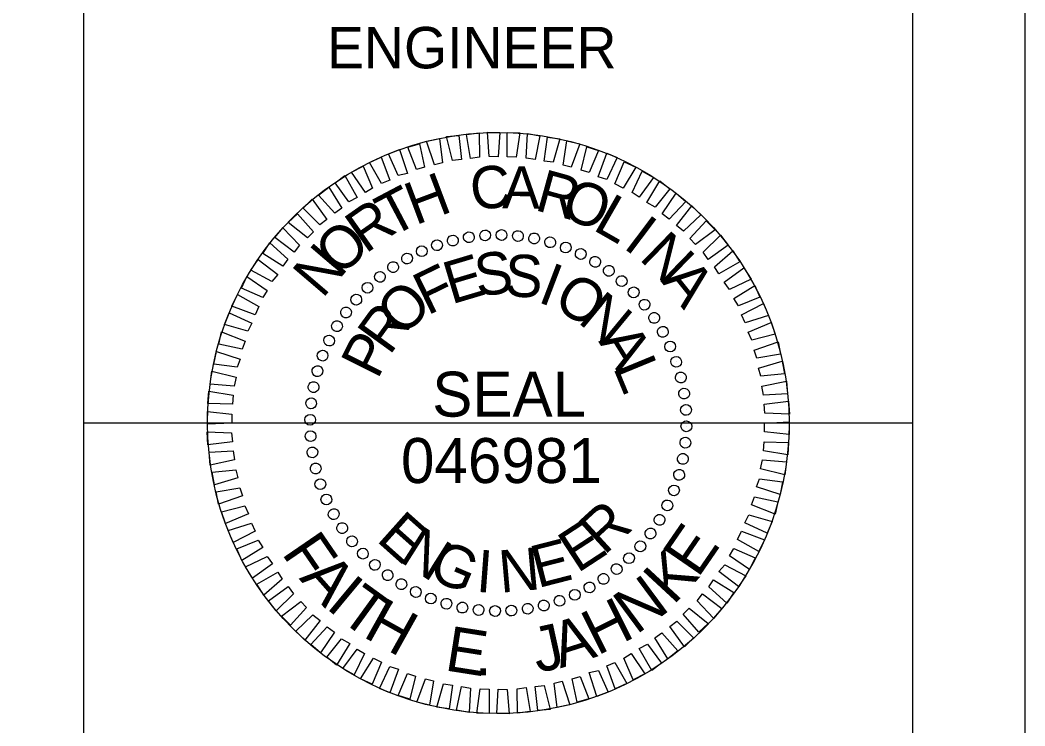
# Model space of a CAD drawing. Extents: x 1184048.9 to 1184122, y 1246638.9 to 1246660.6.
# Drawn here: x 1184112.634 to 1184115.034, y 1246656.132 to 1246657.819 of the extents above; entities that cross this region are included whole.
import ezdxf

# ---------------------------------------------------------------- set-up
doc = ezdxf.new("R2010")
doc.units = 0
for name, color, linetype in [('Scratch_Level_3', 7, 'Continuous'), ('Sheet PE Seal CELL', 7, 'Continuous'), ('Sheet Plan CELL', 7, 'Continuous'), ('Sheet Plot Border Outside CELL', 7, 'Continuous')]:
    doc.layers.add(name, color=color, linetype=linetype)

msp = doc.modelspace()

# ---------------------------------------------------------------- linework, layer by layer
at = {"layer": 'Scratch_Level_3'}
msp.add_line((1184114.7665, 1246656.856), (1184112.7859, 1246656.856), dxfattribs=at)
msp.add_circle((1184113.7762, 1246656.856), 0.6945, dxfattribs=at)
at = {"layer": 'Sheet PE Seal CELL'}
for p, q in [((1184113.6669, 1246657.2923), (1184113.6669, 1246657.2923)), ((1184113.7063, 1246657.2995), (1184113.7063, 1246657.2995)), ((1184113.7448, 1246657.3048), (1184113.7448, 1246657.3048)), ((1184113.7843, 1246657.3057), (1184113.7843, 1246657.3057)), ((1184113.8237, 1246657.3031), (1184113.8237, 1246657.3031)), ((1184113.8622, 1246657.2968), (1184113.8622, 1246657.2968)), ((1184113.8998, 1246657.2887), (1184113.8998, 1246657.2887)), ((1184113.5934, 1246657.2672), (1184113.5934, 1246657.2672)), ((1184113.6293, 1246657.2816), (1184113.6293, 1246657.2816)), ((1184113.9375, 1246657.2762), (1184113.9375, 1246657.2762)), ((1184113.9733, 1246657.2601), (1184113.9733, 1246657.2601)), ((1184113.5585, 1246657.2493), (1184113.5585, 1246657.2493)), ((1184114.0082, 1246657.2421), (1184114.0082, 1246657.2421)), ((1184113.5244, 1246657.2287), (1184113.5244, 1246657.2287)), ((1184114.0405, 1246657.2197), (1184114.0405, 1246657.2197)), ((1184113.4931, 1246657.2063), (1184113.4931, 1246657.2063)), ((1184114.0719, 1246657.1955), (1184114.0719, 1246657.1955)), ((1184113.4635, 1246657.1794), (1184113.4635, 1246657.1794)), ((1184114.0996, 1246657.1687), (1184114.0996, 1246657.1687)), ((1184113.4366, 1246657.1516), (1184113.4366, 1246657.1516)), ((1184114.1265, 1246657.1391), (1184114.1265, 1246657.1391)), ((1184113.4124, 1246657.1203), (1184113.4124, 1246657.1203)), ((1184114.1489, 1246657.1077), (1184114.1489, 1246657.1077)), ((1184113.39, 1246657.088), (1184113.39, 1246657.088)), ((1184114.1695, 1246657.0737), (1184114.1695, 1246657.0737)), ((1184113.3721, 1246657.0531), (1184113.3721, 1246657.0531)), ((1184114.1874, 1246657.0388), (1184114.1874, 1246657.0388)), ((1184113.356, 1246657.0173), (1184113.356, 1246657.0173)), ((1184114.2018, 1246657.0029), (1184114.2018, 1246657.0029)), ((1184113.3435, 1246656.9796), (1184113.3435, 1246656.9796)), ((1184114.2125, 1246656.9653), (1184114.2125, 1246656.9653)), ((1184113.3354, 1246656.942), (1184113.3354, 1246656.942)), ((1184114.2197, 1246656.9259), (1184114.2197, 1246656.9259)), ((1184113.3291, 1246656.9035), (1184113.3291, 1246656.9035)), ((1184114.2251, 1246656.8873), (1184114.2251, 1246656.8873)), ((1184113.3264, 1246656.864), (1184113.3264, 1246656.864)), ((1184113.7762, 1246656.856), (1184113.7762, 1246656.856)), ((1184114.226, 1246656.8479), (1184114.226, 1246656.8479)), ((1184113.3273, 1246656.8246), (1184113.3273, 1246656.8246)), ((1184114.2233, 1246656.8085), (1184114.2233, 1246656.8085)), ((1184113.3327, 1246656.7861), (1184113.3327, 1246656.7861)), ((1184114.217, 1246656.77), (1184114.217, 1246656.77)), ((1184113.3399, 1246656.7467), (1184113.3399, 1246656.7467)), ((1184114.2089, 1246656.7323), (1184114.2089, 1246656.7323)), ((1184113.3506, 1246656.709), (1184113.3506, 1246656.709)), ((1184114.1964, 1246656.6947), (1184114.1964, 1246656.6947)), ((1184113.365, 1246656.6732), (1184113.365, 1246656.6732)), ((1184114.1803, 1246656.6589), (1184114.1803, 1246656.6589)), ((1184113.3829, 1246656.6383), (1184113.3829, 1246656.6383)), ((1184114.1624, 1246656.6239), (1184114.1624, 1246656.6239)), ((1184113.4035, 1246656.6042), (1184113.4035, 1246656.6042)), ((1184114.14, 1246656.5917), (1184114.14, 1246656.5917)), ((1184113.4259, 1246656.5729), (1184113.4259, 1246656.5729)), ((1184113.4528, 1246656.5433), (1184113.4528, 1246656.5433)), ((1184114.1158, 1246656.5603), (1184114.1158, 1246656.5603)), ((1184113.4805, 1246656.5164), (1184113.4805, 1246656.5164)), ((1184114.0889, 1246656.5325), (1184114.0889, 1246656.5325)), ((1184113.5119, 1246656.4922), (1184113.5119, 1246656.4922)), ((1184114.0593, 1246656.5057), (1184114.0593, 1246656.5057)), ((1184113.5441, 1246656.4698), (1184113.5441, 1246656.4698)), ((1184114.028, 1246656.4833), (1184114.028, 1246656.4833)), ((1184113.5791, 1246656.4519), (1184113.5791, 1246656.4519)), ((1184113.959, 1246656.4447), (1184113.959, 1246656.4447)), ((1184113.9939, 1246656.4627), (1184113.9939, 1246656.4627)), ((1184113.6149, 1246656.4358), (1184113.6149, 1246656.4358)), ((1184113.6526, 1246656.4232), (1184113.6526, 1246656.4232)), ((1184113.8855, 1246656.4197), (1184113.8855, 1246656.4197)), ((1184113.9231, 1246656.4304), (1184113.9231, 1246656.4304)), ((1184113.6902, 1246656.4152), (1184113.6902, 1246656.4152)), ((1184113.7287, 1246656.4089), (1184113.7287, 1246656.4089)), ((1184113.7681, 1246656.4062), (1184113.7681, 1246656.4062)), ((1184113.8076, 1246656.4071), (1184113.8076, 1246656.4071)), ((1184113.8461, 1246656.4125), (1184113.8461, 1246656.4125))]:
    msp.add_line(p, q, dxfattribs=at)
for points in [[(1184113.7099, 1246657.4885), (1184113.7, 1246657.5459), (1184113.7305, 1246657.5494), (1184113.7314, 1246657.4912)], [(1184113.7547, 1246657.493), (1184113.7502, 1246657.5512), (1184113.7798, 1246657.5503), (1184113.7762, 1246657.4921)], [(1184113.7977, 1246657.4921), (1184113.7977, 1246657.5503), (1184113.8273, 1246657.5494), (1184113.8192, 1246657.4912)], [(1184113.8425, 1246657.4894), (1184113.8461, 1246657.5477), (1184113.8756, 1246657.5423), (1184113.864, 1246657.4858)], [(1184113.5809, 1246657.4616), (1184113.5603, 1246657.5154), (1184113.5881, 1246657.5235), (1184113.5997, 1246657.4679)], [(1184113.6239, 1246657.4733), (1184113.6051, 1246657.5297), (1184113.6355, 1246657.536), (1184113.6427, 1246657.4778)], [(1184113.6669, 1246657.4831), (1184113.6526, 1246657.5405), (1184113.6821, 1246657.5432), (1184113.6884, 1246657.4858)], [(1184113.8855, 1246657.4822), (1184113.8936, 1246657.5396), (1184113.9231, 1246657.5351), (1184113.907, 1246657.4796)], [(1184113.9312, 1246657.4724), (1184113.9402, 1246657.5306), (1184113.9706, 1246657.5235), (1184113.95, 1246657.4679)], [(1184113.537, 1246657.4473), (1184113.5137, 1246657.4993), (1184113.5406, 1246657.51), (1184113.5594, 1246657.4527)], [(1184113.9742, 1246657.4607), (1184113.9876, 1246657.5163), (1184114.0154, 1246657.5073), (1184113.993, 1246657.4545)], [(1184114.0145, 1246657.4446), (1184114.0351, 1246657.5011), (1184114.0602, 1246657.4903), (1184114.0351, 1246657.4383)], [(1184113.4976, 1246657.4285), (1184113.4689, 1246657.4787), (1184113.4967, 1246657.4912), (1184113.5173, 1246657.4366)], [(1184114.0548, 1246657.4276), (1184114.0772, 1246657.4805), (1184114.105, 1246657.4679), (1184114.0745, 1246657.4177)], [(1184113.459, 1246657.407), (1184113.4259, 1246657.4554), (1184113.4537, 1246657.4697), (1184113.4761, 1246657.4177)], [(1184114.0961, 1246657.407), (1184114.1202, 1246657.4581), (1184114.1471, 1246657.4428), (1184114.1131, 1246657.3962)], [(1184113.4196, 1246657.3846), (1184113.3865, 1246657.4303), (1184113.4098, 1246657.4473), (1184113.4393, 1246657.3953)], [(1184114.131, 1246657.3828), (1184114.1624, 1246657.4348), (1184114.1856, 1246657.4159), (1184114.1507, 1246657.372)], [(1184113.3856, 1246657.3577), (1184113.347, 1246657.4007), (1184113.3712, 1246657.4195), (1184113.4026, 1246657.3694)], [(1184114.1677, 1246657.3559), (1184114.2009, 1246657.4052), (1184114.2242, 1246657.3855), (1184114.1847, 1246657.3434)], [(1184113.3497, 1246657.3299), (1184113.3103, 1246657.3694), (1184113.3318, 1246657.3909), (1184113.3668, 1246657.3425)], [(1184113.3202, 1246657.2986), (1184113.2745, 1246657.3353), (1184113.2969, 1246657.3559), (1184113.3345, 1246657.3129)], [(1184114.2018, 1246657.3281), (1184114.2385, 1246657.3747), (1184114.26, 1246657.3532), (1184114.2188, 1246657.3147)], [(1184114.234, 1246657.2968), (1184114.2726, 1246657.3389), (1184114.2941, 1246657.3174), (1184114.2475, 1246657.2825)], [(1184113.2888, 1246657.2645), (1184113.2422, 1246657.2995), (1184113.2619, 1246657.3228), (1184113.3013, 1246657.2807)], [(1184113.2619, 1246657.2305), (1184113.2135, 1246657.2609), (1184113.2306, 1246657.2869), (1184113.2736, 1246657.2475)], [(1184114.2654, 1246657.2645), (1184114.3066, 1246657.3048), (1184114.3254, 1246657.2807), (1184114.2779, 1246657.2466)], [(1184114.2923, 1246657.2296), (1184114.3362, 1246657.2672), (1184114.3532, 1246657.2412), (1184114.303, 1246657.2126)], [(1184113.235, 1246657.1946), (1184113.1849, 1246657.2215), (1184113.2028, 1246657.2466), (1184113.2494, 1246657.2108)], [(1184114.3156, 1246657.1929), (1184114.363, 1246657.2269), (1184114.3801, 1246657.2), (1184114.3281, 1246657.1749)], [(1184113.2135, 1246657.1561), (1184113.1625, 1246657.1785), (1184113.1759, 1246657.2063), (1184113.2243, 1246657.1731)], [(1184113.1956, 1246657.1149), (1184113.1401, 1246657.1355), (1184113.1535, 1246657.1633), (1184113.2046, 1246657.1346)], [(1184114.3389, 1246657.1534), (1184114.389, 1246657.1848), (1184114.4007, 1246657.157), (1184114.3496, 1246657.1364)], [(1184114.3568, 1246657.1149), (1184114.4096, 1246657.1418), (1184114.4213, 1246657.1131), (1184114.3657, 1246657.0952)], [(1184113.1777, 1246657.0755), (1184113.1222, 1246657.0916), (1184113.1338, 1246657.1194), (1184113.1876, 1246657.0943)], [(1184114.3729, 1246657.0728), (1184114.4276, 1246657.0961), (1184114.4374, 1246657.0683), (1184114.3819, 1246657.054)], [(1184113.1643, 1246657.0325), (1184113.1087, 1246657.0441), (1184113.115, 1246657.0737), (1184113.1714, 1246657.0513)], [(1184114.3872, 1246657.0298), (1184114.4446, 1246657.0504), (1184114.4499, 1246657.0208), (1184114.3935, 1246657.011)], [(1184113.1526, 1246656.9895), (1184113.0971, 1246656.9966), (1184113.1033, 1246657.0271), (1184113.1598, 1246657.0083)], [(1184114.398, 1246656.9868), (1184114.4544, 1246657.0038), (1184114.4598, 1246656.9734), (1184114.4034, 1246656.968)], [(1184113.1455, 1246656.9438), (1184113.0881, 1246656.9492), (1184113.0917, 1246656.9796), (1184113.1499, 1246656.9653)], [(1184114.406, 1246656.9438), (1184114.4643, 1246656.9563), (1184114.467, 1246656.9259), (1184114.4096, 1246656.9223)], [(1184113.141, 1246656.9008), (1184113.0827, 1246656.9026), (1184113.0845, 1246656.9321), (1184113.1428, 1246656.9223)], [(1184114.4114, 1246656.9008), (1184114.4697, 1246656.9079), (1184114.4715, 1246656.8775), (1184114.4132, 1246656.8793)], [(1184113.1401, 1246656.856), (1184113.0818, 1246656.8533), (1184113.0818, 1246656.8838), (1184113.1401, 1246656.8775)], [(1184114.4123, 1246656.856), (1184114.4706, 1246656.8587), (1184114.4706, 1246656.8282), (1184114.4123, 1246656.8345)], [(1184113.141, 1246656.8112), (1184113.0827, 1246656.804), (1184113.0809, 1246656.8345), (1184113.1392, 1246656.8327)], [(1184114.4114, 1246656.8112), (1184114.4697, 1246656.8094), (1184114.4679, 1246656.7798), (1184114.4096, 1246656.7897)], [(1184113.1464, 1246656.7682), (1184113.0881, 1246656.7556), (1184113.0854, 1246656.7861), (1184113.1428, 1246656.7897)], [(1184114.4069, 1246656.7682), (1184114.4643, 1246656.7628), (1184114.4607, 1246656.7323), (1184114.4025, 1246656.7467)], [(1184113.1544, 1246656.7252), (1184113.098, 1246656.7082), (1184113.0926, 1246656.7386), (1184113.149, 1246656.744)], [(1184114.3998, 1246656.7225), (1184114.4553, 1246656.7153), (1184114.4491, 1246656.6849), (1184114.3926, 1246656.7037)], [(1184113.1652, 1246656.6822), (1184113.1078, 1246656.6616), (1184113.1024, 1246656.6911), (1184113.1589, 1246656.701)], [(1184114.3881, 1246656.6795), (1184114.4437, 1246656.6678), (1184114.4374, 1246656.6383), (1184114.381, 1246656.6607)], [(1184113.1795, 1246656.6392), (1184113.1248, 1246656.6159), (1184113.115, 1246656.6436), (1184113.1705, 1246656.658)], [(1184114.3747, 1246656.6365), (1184114.4302, 1246656.6203), (1184114.4186, 1246656.5926), (1184114.3648, 1246656.6177)], [(1184113.1956, 1246656.5971), (1184113.1428, 1246656.5702), (1184113.1311, 1246656.5988), (1184113.1867, 1246656.6168)], [(1184114.3568, 1246656.5971), (1184114.4123, 1246656.5764), (1184114.3989, 1246656.5487), (1184114.3478, 1246656.5773)], [(1184113.2135, 1246656.5585), (1184113.1634, 1246656.5272), (1184113.1517, 1246656.5549), (1184113.2028, 1246656.5756)], [(1184114.3389, 1246656.5558), (1184114.3899, 1246656.5334), (1184114.3765, 1246656.5057), (1184114.3281, 1246656.5388)], [(1184113.2368, 1246656.5191), (1184113.1894, 1246656.4851), (1184113.1723, 1246656.5119), (1184113.2243, 1246656.537)], [(1184114.3173, 1246656.5173), (1184114.3675, 1246656.4904), (1184114.3496, 1246656.4653), (1184114.303, 1246656.5012)], [(1184113.2601, 1246656.4824), (1184113.2162, 1246656.4447), (1184113.1992, 1246656.4707), (1184113.2494, 1246656.4994)], [(1184114.2905, 1246656.4815), (1184114.3389, 1246656.451), (1184114.3218, 1246656.425), (1184114.2788, 1246656.4645)], [(1184113.287, 1246656.4474), (1184113.2458, 1246656.4071), (1184113.227, 1246656.4313), (1184113.2745, 1246656.4653)], [(1184114.2636, 1246656.4474), (1184114.3102, 1246656.4125), (1184114.2905, 1246656.3892), (1184114.251, 1246656.4313)], [(1184113.3184, 1246656.4152), (1184113.2798, 1246656.3731), (1184113.2583, 1246656.3946), (1184113.3049, 1246656.4295)], [(1184113.3506, 1246656.3838), (1184113.3139, 1246656.3372), (1184113.2924, 1246656.3587), (1184113.3336, 1246656.3973)], [(1184114.2322, 1246656.4134), (1184114.2779, 1246656.3767), (1184114.2555, 1246656.356), (1184114.2179, 1246656.3991)], [(1184114.2027, 1246656.382), (1184114.2421, 1246656.3426), (1184114.2206, 1246656.3211), (1184114.1856, 1246656.3695)], [(1184113.3847, 1246656.356), (1184113.3515, 1246656.3068), (1184113.3282, 1246656.3265), (1184113.3676, 1246656.3686)], [(1184114.1668, 1246656.3543), (1184114.2054, 1246656.3112), (1184114.1812, 1246656.2924), (1184114.1498, 1246656.3426)], [(1184113.4214, 1246656.3292), (1184113.39, 1246656.2772), (1184113.3668, 1246656.296), (1184113.4017, 1246656.3399)], [(1184114.1328, 1246656.3274), (1184114.1659, 1246656.2817), (1184114.1426, 1246656.2647), (1184114.1131, 1246656.3166)], [(1184113.4563, 1246656.305), (1184113.4322, 1246656.2539), (1184113.4053, 1246656.2691), (1184113.4393, 1246656.3157)], [(1184114.0934, 1246656.305), (1184114.1265, 1246656.2566), (1184114.0987, 1246656.2423), (1184114.0763, 1246656.2942)], [(1184113.4976, 1246656.2844), (1184113.4752, 1246656.2315), (1184113.4474, 1246656.2441), (1184113.4778, 1246656.2942)], [(1184114.0548, 1246656.2835), (1184114.0835, 1246656.2333), (1184114.0557, 1246656.2208), (1184114.0351, 1246656.2754)], [(1184113.5379, 1246656.2673), (1184113.5173, 1246656.2109), (1184113.4922, 1246656.2217), (1184113.5173, 1246656.2736)], [(1184113.5782, 1246656.2512), (1184113.5648, 1246656.1957), (1184113.537, 1246656.2046), (1184113.5594, 1246656.2575)], [(1184113.9715, 1246656.2503), (1184113.9921, 1246656.1966), (1184113.9643, 1246656.1885), (1184113.9527, 1246656.2441)], [(1184114.0154, 1246656.2647), (1184114.0387, 1246656.2127), (1184114.0118, 1246656.2019), (1184113.993, 1246656.2593)], [(1184113.6212, 1246656.2396), (1184113.6122, 1246656.1813), (1184113.5818, 1246656.1885), (1184113.6024, 1246656.2441)], [(1184113.6669, 1246656.2297), (1184113.6588, 1246656.1724), (1184113.6293, 1246656.1769), (1184113.6454, 1246656.2324)], [(1184113.7099, 1246656.2225), (1184113.7063, 1246656.1643), (1184113.6767, 1246656.1697), (1184113.6884, 1246656.2261)], [(1184113.8855, 1246656.2288), (1184113.8998, 1246656.1715), (1184113.8703, 1246656.1688), (1184113.864, 1246656.2261)], [(1184113.9285, 1246656.2387), (1184113.9473, 1246656.1822), (1184113.9169, 1246656.176), (1184113.9097, 1246656.2342)], [(1184113.7547, 1246656.2199), (1184113.7547, 1246656.1616), (1184113.7251, 1246656.1625), (1184113.7332, 1246656.2208)], [(1184113.7977, 1246656.219), (1184113.8022, 1246656.1607), (1184113.7726, 1246656.1616), (1184113.7762, 1246656.2199)], [(1184113.8425, 1246656.2234), (1184113.8524, 1246656.1661), (1184113.8219, 1246656.1625), (1184113.821, 1246656.2208)]]:
    msp.add_lwpolyline(points, close=True, dxfattribs=at)
for centre, major_axis in [((1184113.6675, 1246657.292), (-0.0031, 0.0125)), ((1184113.7059, 1246657.2999), (-0.002, 0.0127)), ((1184113.7449, 1246657.3043), (-0.0009, 0.0129)), ((1184113.784, 1246657.3053), (0.0002, 0.0129)), ((1184113.8232, 1246657.3029), (0.0013, 0.0128)), ((1184113.8619, 1246657.2971), (0.0025, 0.0127)), ((1184113.6299, 1246657.2809), (-0.0042, 0.0122)), ((1184113.9001, 1246657.288), (0.0036, 0.0124)), ((1184113.9373, 1246657.2755), (0.0046, 0.012)), ((1184113.5583, 1246657.249), (-0.0063, 0.0113)), ((1184113.5934, 1246657.2665), (-0.0052, 0.0118)), ((1184113.9732, 1246657.2599), (0.0057, 0.0116)), ((1184113.5249, 1246657.2286), (-0.0072, 0.0107)), ((1184114.0077, 1246657.2412), (0.0066, 0.0111)), ((1184114.0404, 1246657.2196), (0.0076, 0.0104)), ((1184113.4934, 1246657.2052), (-0.0081, 0.01)), ((1184113.464, 1246657.1793), (-0.00896, 0.00928)), ((1184114.071, 1246657.1952), (0.00846, 0.00974)), ((1184113.437, 1246657.1508), (-0.00974, 0.00846)), ((1184114.0995, 1246657.1682), (0.00928, 0.00896)), ((1184114.1255, 1246657.1388), (0.01, 0.0081)), ((1184113.4126, 1246657.1201), (-0.0104, 0.0076)), ((1184114.1488, 1246657.1073), (0.0107, 0.0072)), ((1184113.391, 1246657.0874), (-0.0111, 0.0066)), ((1184113.3723, 1246657.053), (-0.0116, 0.0057)), ((1184114.1693, 1246657.0739), (0.0113, 0.0063)), ((1184114.1868, 1246657.0388), (0.0118, 0.0052)), ((1184113.3566, 1246657.017), (-0.012, 0.0046)), ((1184113.3442, 1246656.9799), (-0.0124, 0.0036)), ((1184114.2011, 1246657.0023), (0.0122, 0.0042)), ((1184114.2123, 1246656.9647), (0.0125, 0.0031)), ((1184113.3351, 1246656.9417), (-0.0127, 0.0025)), ((1184114.2201, 1246656.9263), (0.0127, 0.002)), ((1184113.3293, 1246656.903), (-0.0128, 0.0013)), ((1184114.2245, 1246656.8873), (0.0129, 0.0009)), ((1184113.3269, 1246656.8638), (-0.0129, 0.0002)), ((1184114.2255, 1246656.8481), (0.0129, -0.0002)), ((1184113.3279, 1246656.8246), (-0.0129, -0.0009)), ((1184114.2231, 1246656.809), (0.0128, -0.0013)), ((1184113.3323, 1246656.7857), (-0.0127, -0.002)), ((1184114.2173, 1246656.7702), (0.0127, -0.0025)), ((1184113.3401, 1246656.7473), (-0.0125, -0.0031)), ((1184114.2082, 1246656.7321), (0.0124, -0.0036)), ((1184113.3513, 1246656.7097), (-0.0122, -0.0042)), ((1184114.1958, 1246656.6949), (0.012, -0.0046)), ((1184113.3656, 1246656.6732), (-0.0118, -0.0052)), ((1184114.1801, 1246656.659), (0.0116, -0.0057)), ((1184113.3831, 1246656.6381), (-0.0113, -0.0063)), ((1184114.1614, 1246656.6245), (0.0111, -0.0066)), ((1184113.4036, 1246656.6047), (-0.0107, -0.0072)), ((1184113.4269, 1246656.5732), (-0.01, -0.0081)), ((1184114.1398, 1246656.5918), (0.0104, -0.0076)), ((1184114.1154, 1246656.5611), (0.00974, -0.00846)), ((1184113.4529, 1246656.5438), (-0.00928, -0.00896)), ((1184114.0884, 1246656.5327), (0.00896, -0.00928)), ((1184113.4814, 1246656.5168), (-0.00846, -0.00974)), ((1184114.059, 1246656.5067), (0.0081, -0.01)), ((1184113.512, 1246656.4924), (-0.0076, -0.0104)), ((1184114.0275, 1246656.4834), (0.0072, -0.0107)), ((1184113.5447, 1246656.4708), (-0.0066, -0.0111)), ((1184113.5792, 1246656.4521), (-0.0057, -0.0116)), ((1184113.9941, 1246656.4629), (0.0063, -0.0113)), ((1184113.6151, 1246656.4364), (-0.0046, -0.012)), ((1184113.9225, 1246656.4311), (0.0042, -0.0122)), ((1184113.959, 1246656.4454), (0.0052, -0.0118)), ((1184113.6523, 1246656.424), (-0.0036, -0.0124)), ((1184113.6904, 1246656.4148), (-0.0025, -0.0127)), ((1184113.7292, 1246656.409), (-0.0013, -0.0128)), ((1184113.7684, 1246656.4066), (-0.0002, -0.0129)), ((1184113.8075, 1246656.4077), (0.0009, -0.0129)), ((1184113.8465, 1246656.4121), (0.002, -0.0127)), ((1184113.8849, 1246656.4199), (0.0031, -0.0125))]:
    msp.add_ellipse(centre, major_axis=major_axis, ratio=0.999708, dxfattribs=at)
at = {"layer": 'Sheet Plan CELL'}
for p, q in [((1184112.7855, 1246639.3047), (1184112.786, 1246660.1998)), ((1184114.7661, 1246639.3047), (1184114.7666, 1246660.1998))]:
    msp.add_line(p, q, dxfattribs=at)
at = {"layer": 'Sheet Plot Border Outside CELL'}
msp.add_lwpolyline([(1184081.364, 1246660.6454), (1184115.034, 1246660.6454), (1184115.034, 1246638.8591), (1184081.364, 1246638.8591)], close=True, dxfattribs=at)

# ---------------------------------------------------------------- texts
at = {"layer": 'Sheet PE Seal CELL'}
for s, height, rotation, p in [('H', 0.1016, 20.6195, (1184113.5782, 1246657.3281)), ('C', 0.1011, 6.2199, (1184113.7144, 1246657.364)), ('A', 0.101, 359.0203, (1184113.7852, 1246657.3694)), ('R', 0.1014, 344.6211, (1184113.8604, 1246657.3658)), ('T', 0.1018, 27.8198, (1184113.52, 1246657.2986)), ('O', 0.1016, 337.4212, (1184113.9204, 1246657.3523)), ('L', 0.1019, 330.2209, (1184113.9993, 1246657.3192)), ('R', 0.1021, 35.0205, (1184113.459, 1246657.2592)), ('O', 0.1022, 42.2217, (1184113.3972, 1246657.2036)), ('I', 0.1021, 323.0201, (1184114.0719, 1246657.2762)), ('N', 0.1022, 315.8189, (1184114.1104, 1246657.2484)), ('N', 0.1021, 49.4235, (1184113.356, 1246657.1516)), ('E', 0.1014, 16.6111, (1184113.6642, 1246657.1391)), ('S', 0.1011, 7.2556, (1184113.726, 1246657.1579)), ('S', 0.101, 357.9004, (1184113.7905, 1246657.1588)), ('F', 0.1018, 25.967, (1184113.6069, 1246657.1122)), ('I', 0.1016, 339.1896, (1184113.8676, 1246657.1463)), ('A', 0.1021, 308.6172, (1184114.1632, 1246657.1955)), ('O', 0.1022, 44.6812, (1184113.5477, 1246657.0594)), ('O', 0.1019, 329.8335, (1184113.9034, 1246657.1337)), ('N', 0.1021, 320.4766, (1184113.9635, 1246657.0979)), ('R', 0.102, 54.0396, (1184113.5164, 1246657.0155)), ('P', 0.1017, 63.3989, (1184113.4877, 1246656.9581)), ('A', 0.1019, 301.7603, (1184114.0145, 1246657.0513)), ('L', 0.1016, 292.4008, (1184114.0495, 1246656.9895)), ('SEAL', 0.10748, 360, (1184113.6185, 1246656.8712)), ('046981', 0.10748, 360, (1184113.5438, 1246656.7125)), ('R', 0.1022, 42.4814, (1184114.0289, 1246656.5379)), ('E', 0.1021, 318.2769, (1184113.4823, 1246656.5756)), ('E', 0.102, 33.1241, (1184113.9652, 1246656.4958)), ('E', 0.1085, 55.493, (1184114.2529, 1246656.4834)), ('F', 0.1085, 304.4142, (1184113.2571, 1246656.5452)), ('N', 0.102, 327.634, (1184113.5361, 1246656.5272)), ('G', 0.1017, 336.9902, (1184113.6042, 1246656.4869)), ('E', 0.1013, 14.4118, (1184113.8703, 1246656.4609)), ('I', 0.1011, 355.7012, (1184113.7215, 1246656.4528)), ('N', 0.1011, 5.0564, (1184113.7816, 1246656.4501)), ('K', 0.1087, 47.2091, (1184114.1942, 1246656.4186)), ('A', 0.1086, 311.4309, (1184113.299, 1246656.4841)), ('I', 0.1087, 320.2712, (1184113.3618, 1246656.4152)), ('N', 0.1086, 36.4833, (1184114.1055, 1246656.3485)), ('T', 0.1086, 324.0731, (1184113.3919, 1246656.3887)), ('H', 0.1084, 330.8733, (1184113.45, 1246656.3465)), ('H', 0.1083, 26.4993, (1184114.0125, 1246656.2991)), ('J', 0.1077, 12.4012, (1184113.8698, 1246656.2583)), ('A', 0.1079, 17.659, (1184113.9242, 1246656.2693)), ('E', 0.1076, 351.0577, (1184113.6458, 1246656.2652)), ('.', 0.1075, 358.167, (1184113.7199, 1246656.2536))]:
    msp.add_text(s, height=height, rotation=rotation, dxfattribs=at).set_placement(p)
at = {"layer": 'Sheet Plan CELL'}
msp.add_text('ENGINEER', height=0.09903, rotation=0, dxfattribs=at).set_placement((1184113.367, 1246657.7037))

doc.saveas('drawing.dxf')
